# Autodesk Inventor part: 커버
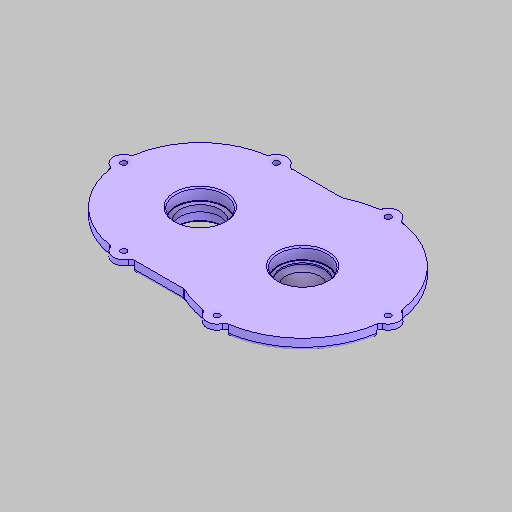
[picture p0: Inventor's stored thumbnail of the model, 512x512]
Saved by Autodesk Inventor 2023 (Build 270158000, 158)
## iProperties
Created: 2025-09
Part Number: 커버
Material: 알루미늄 6061
Document SubType Name: Modeling
Designer: home
Density: 2.7 g/cm^3
Appearance: 기본값
Author: jhkim
Sending System: Autodesk Inventor 2026
Preprocessor: ST-DEVELOPER v20.1
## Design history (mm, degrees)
feature "솔리드1"
node "솔리드2"
